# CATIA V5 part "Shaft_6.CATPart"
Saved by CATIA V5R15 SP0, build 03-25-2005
Part number: Shaft_6
Bounding box of the stored display mesh (mm): x -23.8 to 23.8, y -23.8 to 23.8, z 0 to 474
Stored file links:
  E:\#01 CATIA Lecture Materials\#06 DMU\#11 DMU Page01 KIN EX11\Shaft_6.CATPart
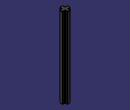
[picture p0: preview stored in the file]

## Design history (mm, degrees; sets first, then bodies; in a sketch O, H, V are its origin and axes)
Body1 (main body)
  Sketch1 on xy-plane, origin (0, 0, 0), H (1, 0, 0), V (0, 1, 0)
    arc A1 centre (0, 0) radius 23.8 from (21.9289, -9.25) to (21.9289, 9.25) ccw
    line L1 (-21.9289, 9.25) -> (-9.25, 9.25)
    line L2 (21.9289, -9.25) -> (9.25, -9.25)
    line L3 (9.25, 21.9289) -> (9.25, 9.25)
    line L4 (-9.25, -21.9289) -> (-9.25, -9.25)
    point P4 (-9.25, -21.9289)
    arc A2 centre (0, 0) radius 23.8 from (-9.25, -21.9289) to (9.25, -21.9289) ccw
    point P6 (-21.9289, 9.25)
    arc A3 centre (0, 0) radius 23.8 from (-21.9289, 9.25) to (-21.9289, -9.25) ccw
    point P8 (9.25, 21.9289)
    arc A4 centre (0, 0) radius 23.8 from (9.25, 21.9289) to (-9.25, 21.9289) ccw
    point P9 (-9.25, 9.25)
    line L5 (9.25, 9.25) -> (21.9289, 9.25)
    line L6 (9.25, -9.25) -> (9.25, -21.9289)
    line L7 (-9.25, 9.25) -> (-9.25, 21.9289)
    point P12 (-9.25, -9.25)
    line L8 (-9.25, -9.25) -> (-21.9289, -9.25)
    radius A1 = 23.8
    distance L1 L2 = 18.5
    distance H L1 = 9.25
    distance L3 L4 = 18.5
    distance V L3 = 9.25
    horizontal: L1 H, L2 H, L5 H, L8 H
    vertical: L3 V, L4 V, L6 V, L7 V
    coincidence: A1 P4, A1 A2, A1 P6, A1 A3, A1 P8, A1 A4, L4 P9, L1 L5, L3 L6, L2 P12, L4 L7, L2 L8
  Pad1: profile Sketch1, direction (0, 0, 1), length 474
  Fillet1: radius 2, on edge [face of Pad1 | face of Pad1] (x4)
  Fillet2: radius 2, on face of Pad1 (x2)
  Fillet3: radius 2, on edge [face of Pad1 from Sketch1.L5 | face of Pad1 from Sketch1.A1]; edge [face of Pad1 from Sketch1.A4 | face of Pad1 from Sketch1.L3]; edge [face of Pad1 from Sketch1.L7 | face of Pad1 from Sketch1.A4]; edge [face of Pad1 from Sketch1.A1 | face of Pad1 from Sketch1.L2]; edge [face of Pad1 from Sketch1.A3 | face of Pad1 from Sketch1.L1]; edge [face of Pad1 from Sketch1.L6 | face of Pad1 from Sketch1.A2]; edge [face of Pad1 from Sketch1.A2 | face of Pad1 from Sketch1.L4]; edge [face of Pad1 from Sketch1.L8 | face of Pad1 from Sketch1.A3]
